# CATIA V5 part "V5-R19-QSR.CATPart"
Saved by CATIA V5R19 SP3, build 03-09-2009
Part number: Part1
Bounding box of the stored display mesh (mm): x -89.875 to 158.587, y -19.615 to 59.518, z -3.611 to 3.914
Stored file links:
  C:\Templates\V5-R19-QSR.CATPart
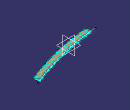
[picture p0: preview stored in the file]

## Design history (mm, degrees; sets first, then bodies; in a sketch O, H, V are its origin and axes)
Set1 "Tesselation und Rückführung"
  Plane1: type Normal, Curve Sketch2
  Sketch1 on Plane1, origin (39.1312, 9.5821, 0), H (-0.2378, 0.9713, 0), V (0, 0, 1)
    point P1 (-10, 0)
    point P2 (10.0011, 3.8173)
    point P3 (10.0011, -3.8173)
    point P4 (-10, 0)
    line L1 (10.0011, -3.8173) -> (10.0011, 3.8173)
    spline S1 through (10.0011, 3.8173) (0, 2.4661) (-10, 0)
    spline S2 through (10.0011, -3.8173) (0, -2.4661) (-10, 0)
    point P5 (10.0011, 3.8173)
    point P6 (0, 2.4661)
    point P7 (-10, 0)
    point P8 (-10, 0)
    point P9 (10.0011, -3.8173)
    point P10 (0, -2.4661)
    symmetry: P2 P3 H, P1 P4 H, S1 S2 H, P7 P8 H, P5 P9 H, P6 P10 H
    vertical: L1 V
    coincidence: P1 P4, P5 P2, P6 V, P7 P4
  CLDGeom1 "Tessellation.1"
  Line1 "CylinderAxis.1": type PtPt, FirstPoint {point type Coord, Length -157.5099, Length 812.4094, Length -1.6223}, SecondPoint {point type Coord, Length -157.5099, Length 812.4094, Length 1.6223}
  Cylinder1 "Cylinder.Basic Surface Recognition": Center {point type Coord, Length -157.5099, Length 812.4094, Length -1.6223}, Direction Line1, L1 0, L2 3.25, Radius 816.5554
  DatumSurface1 "Surface.mit Power fit"
  Set2 "neuaufbau"
    Extrapol1: ToExtrapol edge of Cylinder1, Support Cylinder1, Length 5
    Extrapol2: ToExtrapol edge of DatumSurface1, Support DatumSurface1, Length 10
    Symmetry1: ToTransfor Extrapol2, Reference xy-plane
    Extrapol3: ToExtrapol edge of Cylinder1, Support Extrapol1, Length 5
    Trim1: Trimmed (Extrapol2; Symmetry1)
    Blend1: StartLimit {blendlimit Curve edge of DatumSurface1}, EndLimit {blendlimit Curve edge of Symmetry1}
    Join1: Elements (Trim1; Blend1)
  Intersect1 "Intersect.Theoretische Kante": ToIntersect1 Extrapol2, ToIntersect2 Extrapol3
Body1 "Dummybsp" (main body)
  Sketch2 on xy-plane, origin (0, 0, 0), H (1, 0, 0), V (0, 1, 0)
    spline S1 through (-73.2444, -14.6941) (60, 10) (150, 40)
  Rib1: profile Sketch1, centre curve Sketch2
  Fillet1: radius 2, on edge [face of Rib1 | face of Rib1] (x2)
  Fillet2: radius 0.1, on edge [face of Rib1 | face of Rib1]
Body2 "neues Solid"
  CloseSurface1: CloseElement Join1
  Split1: SplitPlane Extrapol3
